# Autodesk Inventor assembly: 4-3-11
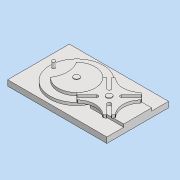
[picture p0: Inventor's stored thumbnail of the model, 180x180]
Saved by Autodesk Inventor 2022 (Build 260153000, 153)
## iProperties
Created: 2021-07
Part Number: 4-3-11
Document SubType Name: Assembly
Designer: DesignLab
Author: DesignLab
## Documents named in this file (5)
- d:\Users\DesignLab\Desktop\ver2022\ch04\4-3-11.iam
- d:\Users\DesignLab\Desktop\ver2022\ch04\03-ベース板_完成.ipt
- d:\Users\DesignLab\Desktop\ver2022\ch04\01-駆動車_完成.ipt
- d:\Users\DesignLab\Desktop\ver2022\ch04\02-従動車_完成.ipt
- d:\Users\DesignLab\Desktop\ver2022\ch04\04-ピン_完成.ipt
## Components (5 placed, 4 different names)
1. 03-ベース板_完成:1 — 回転:1, 回転:2, 駆動車回転
2. 01-駆動車_完成:1 — 回転:1, フラッシュ:1, 駆動車回転
3. 02-従動車_完成:1 — 回転:2, 回転:3
4. 04-ピン_完成:1 — フラッシュ:1
5. 04-ピン_完成:2 — 回転:3
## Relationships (5: RevoluteJoint 3, Flush 1, Angle 1)
- 回転:1 [RevoluteJoint]: 03-ベース板_完成:1 ↔ 01-駆動車_完成:1
- 回転:2 [RevoluteJoint]: 03-ベース板_完成:1 ↔ 02-従動車_完成:1
- フラッシュ:1 [Flush]: 01-駆動車_完成:1 ↔ 04-ピン_完成:1
- 回転:3 [RevoluteJoint]: 02-従動車_完成:1 ↔ 04-ピン_完成:2
- 駆動車回転 [Angle]: 03-ベース板_完成:1 ↔ 01-駆動車_完成:1
